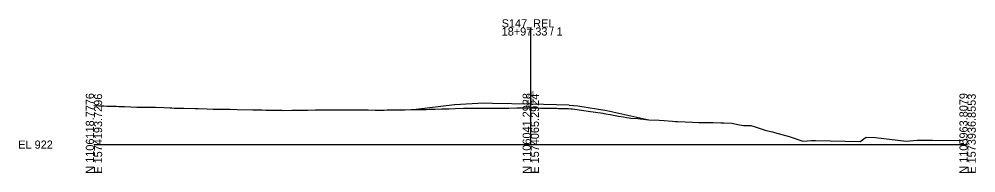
# Model space of a CAD drawing. Extents: x 1557985 to 1558314, y 1113650 to 1118205.
# Drawn here: x 1557985.4 to 1558314, y 1115650.1 to 1115702.9 of the extents above; entities that cross this region are included whole.
import ezdxf

# ---------------------------------------------------------------- set-up
doc = ezdxf.new("R2010")
doc.units = 0
for name, color, linetype in [('RD_GPK_XS_Cell', 7, 'Continuous'), ('RD_XS_EarthShd', 7, 'Continuous'), ('RD_XS_ExGround', 7, 'Continuous'), ('RD_XS_Pave', 7, 'Continuous'), ('RD_XS_TieSlope', 7, 'Continuous'), ('RD_XS_TX_Elev_EX', 7, 'Continuous'), ('RD_XS_TX_Elev_PR', 7, 'Continuous')]:
    doc.layers.add(name, color=color, linetype=linetype)

msp = doc.modelspace()

# ---------------------------------------------------------------- linework, layer by layer
at = {"layer": 'RD_GPK_XS_Cell'}
for p, q in [((1558161.13, 1115659.8), (1558161.13, 1115700.02)), ((1558011.13, 1115659.8), (1558161.13, 1115659.8)), ((1558161.13, 1115659.8), (1558311.13, 1115659.8))]:
    msp.add_line(p, q, dxfattribs=at)
at = {"layer": 'RD_XS_EarthShd'}
for p, q in [((1558144.97, 1115674), (1558134.97, 1115673.4)), ((1558147.97, 1115673.94), (1558144.97, 1115674)), ((1558134.97, 1115673.4), (1558121.72, 1115671.81)), ((1558174.28, 1115673.37), (1558177.28, 1115673.13))]:
    msp.add_line(p, q, dxfattribs=at)
at = {"layer": 'RD_XS_ExGround'}
msp.add_lwpolyline([(1558011.13, 1115673.2), (1558013.06, 1115673.12), (1558013.69, 1115673.09), (1558014.48, 1115673.08), (1558015.66, 1115673.04), (1558017.28, 1115672.98), (1558018.82, 1115672.94), (1558019.69, 1115672.9), (1558021.66, 1115672.83), (1558023.76, 1115672.77), (1558025.85, 1115672.7), (1558026.79, 1115672.69), (1558028.31, 1115672.67), (1558029.29, 1115672.66), (1558030.68, 1115672.63), (1558031.79, 1115672.6), (1558032.3, 1115672.6), (1558035.14, 1115672.5), (1558037.33, 1115672.44), (1558037.92, 1115672.41), (1558038.81, 1115672.36), (1558040.34, 1115672.33), (1558041.97, 1115672.31), (1558045.88, 1115672.24), (1558046.89, 1115672.23), (1558049.96, 1115672.12), (1558052.01, 1115672.02), (1558052.47, 1115672.01), (1558054.73, 1115671.99), (1558056.12, 1115671.97), (1558057.47, 1115671.93), (1558057.87, 1115671.93), (1558060.28, 1115671.85), (1558065.71, 1115671.77), (1558068.79, 1115671.71), (1558070.12, 1115671.64), (1558070.92, 1115671.63), (1558072.66, 1115671.62), (1558075.67, 1115671.58), (1558076.38, 1115671.56), (1558079.08, 1115671.58), (1558079.44, 1115671.58), (1558080.15, 1115671.59), (1558083.69, 1115671.63), (1558084.46, 1115671.67), (1558087.15, 1115671.72), (1558088.56, 1115671.72), (1558088.88, 1115671.71), (1558092.7, 1115671.71), (1558093.87, 1115671.7), (1558097.48, 1115671.73), (1558100.12, 1115671.71), (1558101.12, 1115671.68), (1558102.5, 1115671.71), (1558102.85, 1115671.71), (1558105.32, 1115671.68), (1558107.65, 1115671.66), (1558108.39, 1115671.66), (1558110.83, 1115671.66), (1558111.82, 1115671.68), (1558113.15, 1115671.7), (1558113.87, 1115671.72), (1558114.34, 1115671.73), (1558116.7, 1115671.77), (1558117.81, 1115671.79), (1558120.02, 1115671.8), (1558123.31, 1115671.86), (1558125.17, 1115671.89), (1558126.38, 1115671.91), (1558127.12, 1115671.92), (1558128.32, 1115671.95), (1558130.43, 1115672.03), (1558133.06, 1115672.13), (1558135.11, 1115672.19), (1558138, 1115672.25), (1558139, 1115672.25), (1558139.63, 1115672.25), (1558145.29, 1115672.31), (1558146.12, 1115672.28), (1558149.78, 1115672.25), (1558151.77, 1115672.3), (1558153.61, 1115672.35), (1558156.32, 1115672.37), (1558157.11, 1115672.38), (1558158.48, 1115672.39), (1558161.13, 1115672.38), (1558162.25, 1115672.38), (1558163.11, 1115672.37), (1558164.51, 1115672.36), (1558167.1, 1115672.32), (1558168.81, 1115672.29), (1558170.13, 1115672.25), (1558170.55, 1115672.24), (1558172.21, 1115672.2), (1558174.05, 1115672.16), (1558174.88, 1115672.12), (1558175.44, 1115672.07), (1558179.33, 1115671.56), (1558180.84, 1115671.32), (1558181.65, 1115671.2), (1558182.59, 1115671.05), (1558185.86, 1115670.54), (1558186.16, 1115670.5), (1558186.85, 1115670.4), (1558188.43, 1115670.17), (1558191.23, 1115669.59), (1558192.96, 1115669.28), (1558193.99, 1115669.13), (1558194.96, 1115668.96), (1558195.52, 1115668.91), (1558197.85, 1115668.71), (1558198.72, 1115668.62), (1558201.72, 1115668.35), (1558205.26, 1115668.17), (1558206.9, 1115668.04), (1558209.76, 1115667.84), (1558210.69, 1115667.76), (1558211.51, 1115667.7), (1558214.11, 1115667.59), (1558216.63, 1115667.46), (1558218.78, 1115667.4), (1558221.6, 1115667.35), (1558222.22, 1115667.36), (1558222.53, 1115667.37), (1558223.74, 1115667.34), (1558226.35, 1115667.28), (1558227.42, 1115667.24), (1558230.22, 1115667.19), (1558232.81, 1115666.63), (1558234.23, 1115666.4), (1558236.67, 1115666.39), (1558237.86, 1115665.97), (1558241.22, 1115664.89), (1558241.55, 1115664.73), (1558244.1, 1115664.19), (1558244.85, 1115663.95), (1558249.85, 1115662.6), (1558250.24, 1115662.5), (1558254.54, 1115660.95), (1558257.5, 1115661.23), (1558258.38, 1115661.2), (1558258.85, 1115661.19), (1558274.22, 1115660.9), (1558276.33, 1115662.35), (1558279.49, 1115662.27), (1558290.03, 1115661.02), (1558293.83, 1115661.36), (1558299.04, 1115661.3), (1558308.61, 1115661.16), (1558310.49, 1115661.69), (1558311.13, 1115661.63)], dxfattribs=at)
at = {"layer": 'RD_XS_Pave'}
for p, q in [((1558161.13, 1115673.65), (1558147.97, 1115673.94)), ((1558174.28, 1115673.37), (1558161.13, 1115673.65))]:
    msp.add_line(p, q, dxfattribs=at)
at = {"layer": 'RD_XS_TieSlope'}
for p, q in [((1558177.28, 1115673.13), (1558187.28, 1115671.53)), ((1558187.28, 1115671.53), (1558201.71, 1115668.35))]:
    msp.add_line(p, q, dxfattribs=at)

# ---------------------------------------------------------------- texts
at = {"layer": 'RD_GPK_XS_Cell'}
for s, p in [('S147_REL', (1558151.13, 1115700.02)), ('18+97.33 / 1', (1558151.13, 1115697.22)), ('EL 922', (1557985.13, 1115658.4))]:
    msp.add_text(s, height=2.8, dxfattribs=at).set_placement(p)
for s, p in [('N 1106118.7776', (1558011.13, 1115649.8)), ('E 1574193.7296', (1558013.93, 1115649.8)), ('N 1106041.2928', (1558161.13, 1115649.8)), ('E 1574065.2924', (1558163.93, 1115649.8)), ('N 1105963.8079', (1558311.13, 1115649.8)), ('E 1573936.8553', (1558313.93, 1115649.8))]:
    msp.add_text(s, height=2.8, rotation=90, dxfattribs=at).set_placement(p)
at = {"layer": 'RD_XS_TX_Elev_EX'}
msp.add_text('934.59', height=1, rotation=90, dxfattribs=at).set_placement((1558160.63, 1115672.88))
at = {"layer": 'RD_XS_TX_Elev_PR'}
msp.add_text(' 935.86', height=1, rotation=90, dxfattribs=at).set_placement((1558162.13, 1115673.65))

doc.saveas('drawing.dxf')
